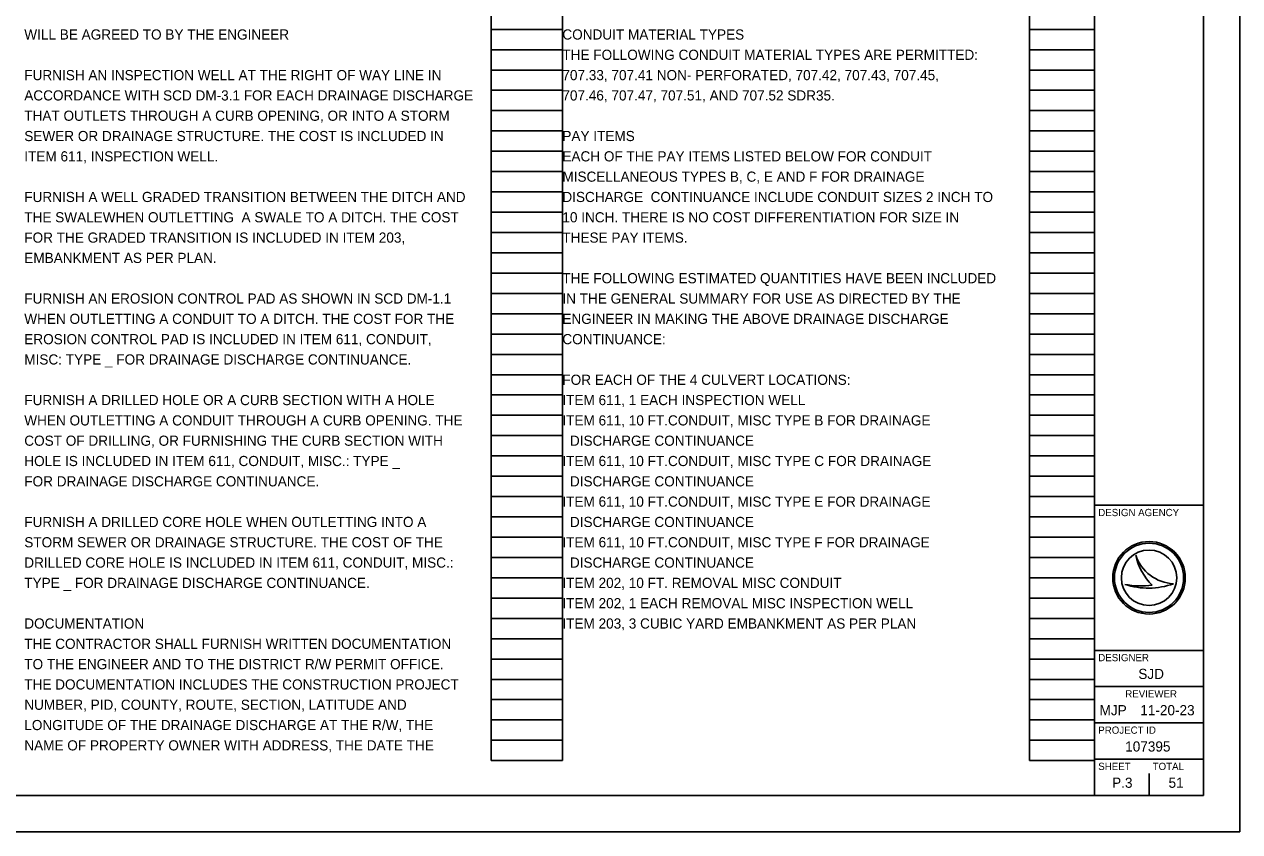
# Model space of a CAD drawing. Extents: x 0 to 34, y 0 to 22.
# Drawn here: x 17.24 to 34, y 0 to 11.13 of the extents above; entities that cross this region are included whole.
import ezdxf

# ---------------------------------------------------------------- set-up
doc = ezdxf.new("R2010")
doc.units = 0
for name, color, linetype in [('SH_Border', 7, 'Continuous'), ('SH_Cut_Line', 7, 'Continuous'), ('SH_Data', 7, 'Continuous'), ('SH_Text', 7, 'Continuous')]:
    doc.layers.add(name, color=color, linetype=linetype)

msp = doc.modelspace()

# ---------------------------------------------------------------- linework, layer by layer
at = {"layer": 'SH_Border'}
for p, q in [((32, 0.5), (32, 21.5)), ((32, 4.5), (33.5, 4.5)), ((32, 2.5), (33.5, 2.5)), ((32, 2), (33.5, 2)), ((32, 1.5), (33.5, 1.5)), ((32, 1), (33.5, 1))]:
    msp.add_line(p, q, dxfattribs=at)
msp.add_lwpolyline([(1.5, 21.5), (33.5, 21.5), (33.5, 0.5), (1.5, 0.5)], close=True, dxfattribs=at)
at = {"layer": 'SH_Cut_Line'}
msp.add_lwpolyline([(0, 0), (34, 0), (34, 22), (0, 22)], close=True, dxfattribs=at)
at = {"layer": 'SH_Data'}
for p, q in [((23.68, 0.98), (23.68, 21.14)), ((24.66, 0.98), (24.66, 21.14)), ((31.1, 0.98), (31.1, 21.14)), ((32, 0.98), (32, 21.14)), ((23.68, 11.06), (24.66, 11.06)), ((31.1, 11.06), (32, 11.06)), ((23.68, 10.78), (24.66, 10.78)), ((31.1, 10.78), (32, 10.78)), ((23.68, 10.5), (24.66, 10.5)), ((31.1, 10.5), (32, 10.5)), ((23.68, 10.22), (24.66, 10.22)), ((31.1, 10.22), (32, 10.22)), ((23.68, 9.94), (24.66, 9.94)), ((31.1, 9.94), (32, 9.94)), ((23.68, 9.66), (24.66, 9.66)), ((31.1, 9.66), (32, 9.66)), ((23.68, 9.38), (24.66, 9.38)), ((31.1, 9.38), (32, 9.38)), ((23.68, 9.1), (24.66, 9.1)), ((31.1, 9.1), (32, 9.1)), ((23.68, 8.82), (24.66, 8.82)), ((31.1, 8.82), (32, 8.82)), ((23.68, 8.54), (24.66, 8.54)), ((31.1, 8.54), (32, 8.54)), ((23.68, 8.26), (24.66, 8.26)), ((31.1, 8.26), (32, 8.26)), ((23.68, 7.98), (24.66, 7.98)), ((31.1, 7.98), (32, 7.98)), ((23.68, 7.7), (24.66, 7.7)), ((31.1, 7.7), (32, 7.7)), ((23.68, 7.42), (24.66, 7.42)), ((31.1, 7.42), (32, 7.42)), ((23.68, 7.14), (24.66, 7.14)), ((31.1, 7.14), (32, 7.14)), ((23.68, 6.86), (24.66, 6.86)), ((31.1, 6.86), (32, 6.86)), ((23.68, 6.58), (24.66, 6.58)), ((31.1, 6.58), (32, 6.58)), ((23.68, 6.3), (24.66, 6.3)), ((31.1, 6.3), (32, 6.3)), ((23.68, 6.02), (24.66, 6.02)), ((31.1, 6.02), (32, 6.02)), ((23.68, 5.74), (24.66, 5.74)), ((31.1, 5.74), (32, 5.74)), ((23.68, 5.46), (24.66, 5.46)), ((31.1, 5.46), (32, 5.46)), ((23.68, 5.18), (24.66, 5.18)), ((31.1, 5.18), (32, 5.18)), ((23.68, 4.9), (24.66, 4.9)), ((31.1, 4.9), (32, 4.9)), ((23.68, 4.62), (24.66, 4.62)), ((31.1, 4.62), (32, 4.62)), ((23.68, 4.34), (24.66, 4.34)), ((31.1, 4.34), (32, 4.34)), ((23.68, 4.06), (24.66, 4.06)), ((31.1, 4.06), (32, 4.06)), ((23.68, 3.78), (24.66, 3.78)), ((31.1, 3.78), (32, 3.78)), ((32.567, 3.81), (32.567, 3.81)), ((23.68, 3.5), (24.66, 3.5)), ((31.1, 3.5), (32, 3.5)), ((32.417, 3.41), (32.417, 3.41)), ((32.75, 3.5), (32.75, 3.5)), ((33.087, 3.419), (33.087, 3.419)), ((23.68, 3.22), (24.66, 3.22)), ((31.1, 3.22), (32, 3.22)), ((23.68, 2.94), (24.66, 2.94)), ((31.1, 2.94), (32, 2.94)), ((23.68, 2.66), (24.66, 2.66)), ((31.1, 2.66), (32, 2.66)), ((23.68, 2.38), (24.66, 2.38)), ((31.1, 2.38), (32, 2.38)), ((23.68, 2.1), (24.66, 2.1)), ((31.1, 2.1), (32, 2.1)), ((23.68, 1.82), (24.66, 1.82)), ((31.1, 1.82), (32, 1.82)), ((23.68, 1.54), (24.66, 1.54)), ((31.1, 1.54), (32, 1.54)), ((23.68, 1.26), (24.66, 1.26)), ((31.1, 1.26), (32, 1.26)), ((23.68, 0.98), (24.66, 0.98)), ((31.1, 0.98), (32, 0.98)), ((32.375, 0.675), (32.375, 0.675)), ((32.75, 0.5), (32.75, 0.8))]:
    msp.add_line(p, q, dxfattribs=at)
for radius in [0.5, 0.477, 0.477, 0.382]:
    msp.add_circle((32.75, 3.5), radius, dxfattribs=at)
for centre, radius, start, end in [((33.116, 3.998), 0.58, 198.9257, 198.9319), ((33.347, 3.97), 0.796, 191.6379, 191.6421), ((33.116, 3.998), 0.58, 198.9319, 267.1657), ((33.347, 3.97), 0.796, 191.6421, 226.0947), ((32.739, 4.37), 1.013, 251.4576, 290.0832), ((32.648, 4.654), 1.266, 259.4964, 259.4995), ((32.739, 4.37), 1.013, 251.4527, 251.4576), ((32.648, 4.654), 1.266, 259.4995, 276.6672)]:
    msp.add_arc(centre, radius, start, end, dxfattribs=at)

# ---------------------------------------------------------------- texts
for s, height, p in [('DESIGN AGENCY', 0.1, (32.05, 4.35)), ('DESIGNER', 0.1, (32.05, 2.35)), ('SJD', 0.14, (32.602, 2.105)), ('REVIEWER', 0.1, (32.422, 1.85)), ('MJP', 0.14, (32.068, 1.605)), ('11-20-23', 0.14, (32.629, 1.605)), ('PROJECT ID', 0.1, (32.05, 1.35)), ('107395', 0.14, (32.421, 1.105)), ('SHEET', 0.1, (32.05, 0.85)), ('TOTAL', 0.1, (32.8, 0.85)), ('P.3', 0.14, (32.241, 0.605)), ('51', 0.14, (33.019, 0.605))]:
    msp.add_text(s, height=height, dxfattribs=at).set_placement(p)
at = {"layer": 'SH_Text'}
for s, p in [('WILL BE AGREED TO BY THE ENGINEER', (17.24, 10.92)), ('CONDUIT MATERIAL TYPES', (24.66, 10.92)), ('THE FOLLOWING CONDUIT MATERIAL TYPES ARE PERMITTED:', (24.66, 10.64)), ('FURNISH AN INSPECTION WELL AT THE RIGHT OF WAY LINE IN', (17.24, 10.36)), ('707.33, 707.41 NON- PERFORATED, 707.42, 707.43, 707.45,', (24.66, 10.36)), ('ACCORDANCE WITH SCD DM-3.1 FOR EACH DRAINAGE DISCHARGE', (17.24, 10.08)), ('707.46, 707.47, 707.51, AND 707.52 SDR35.', (24.66, 10.08)), ('THAT OUTLETS THROUGH A CURB OPENING, OR INTO A STORM', (17.24, 9.8)), ('SEWER OR DRAINAGE STRUCTURE. THE COST IS INCLUDED IN', (17.24, 9.52)), ('PAY ITEMS', (24.66, 9.52)), ('ITEM 611, INSPECTION WELL.', (17.24, 9.24)), ('EACH OF THE PAY ITEMS LISTED BELOW FOR CONDUIT', (24.66, 9.24)), ('MISCELLANEOUS TYPES B, C, E AND F FOR DRAINAGE', (24.66, 8.96)), ('FURNISH A WELL GRADED TRANSITION BETWEEN THE DITCH AND', (17.24, 8.68)), ('DISCHARGE  CONTINUANCE INCLUDE CONDUIT SIZES 2 INCH TO', (24.66, 8.68)), ('THE SWALEWHEN OUTLETTING  A SWALE TO A DITCH. THE COST', (17.24, 8.4)), ('10 INCH. THERE IS NO COST DIFFERENTIATION FOR SIZE IN', (24.66, 8.4)), ('FOR THE GRADED TRANSITION IS INCLUDED IN ITEM 203,', (17.24, 8.12)), ('THESE PAY ITEMS.', (24.66, 8.12)), ('EMBANKMENT AS PER PLAN.', (17.24, 7.84)), ('THE FOLLOWING ESTIMATED QUANTITIES HAVE BEEN INCLUDED', (24.66, 7.56)), ('FURNISH AN EROSION CONTROL PAD AS SHOWN IN SCD DM-1.1', (17.24, 7.28)), ('IN THE GENERAL SUMMARY FOR USE AS DIRECTED BY THE', (24.66, 7.28)), ('WHEN OUTLETTING A CONDUIT TO A DITCH. THE COST FOR THE', (17.24, 7)), ('ENGINEER IN MAKING THE ABOVE DRAINAGE DISCHARGE', (24.66, 7)), ('EROSION CONTROL PAD IS INCLUDED IN ITEM 611, CONDUIT,', (17.24, 6.72)), ('CONTINUANCE:', (24.66, 6.72)), ('MISC: TYPE _ FOR DRAINAGE DISCHARGE CONTINUANCE.', (17.24, 6.44)), ('FOR EACH OF THE 4 CULVERT LOCATIONS:', (24.66, 6.16)), ('FURNISH A DRILLED HOLE OR A CURB SECTION WITH A HOLE', (17.24, 5.88)), ('ITEM 611, 1 EACH INSPECTION WELL', (24.66, 5.88)), ('WHEN OUTLETTING A CONDUIT THROUGH A CURB OPENING. THE', (17.24, 5.6)), ('ITEM 611, 10 FT.CONDUIT, MISC TYPE B FOR DRAINAGE', (24.66, 5.6)), ('COST OF DRILLING, OR FURNISHING THE CURB SECTION WITH', (17.24, 5.32)), ('  DISCHARGE CONTINUANCE', (24.66, 5.32)), ('HOLE IS INCLUDED IN ITEM 611, CONDUIT, MISC.: TYPE _', (17.24, 5.04)), ('ITEM 611, 10 FT.CONDUIT, MISC TYPE C FOR DRAINAGE', (24.66, 5.04)), ('FOR DRAINAGE DISCHARGE CONTINUANCE.', (17.24, 4.76)), ('  DISCHARGE CONTINUANCE', (24.66, 4.76)), ('ITEM 611, 10 FT.CONDUIT, MISC TYPE E FOR DRAINAGE', (24.66, 4.48)), ('FURNISH A DRILLED CORE HOLE WHEN OUTLETTING INTO A', (17.24, 4.2)), ('  DISCHARGE CONTINUANCE', (24.66, 4.2)), ('STORM SEWER OR DRAINAGE STRUCTURE. THE COST OF THE', (17.24, 3.92)), ('ITEM 611, 10 FT.CONDUIT, MISC TYPE F FOR DRAINAGE', (24.66, 3.92)), ('DRILLED CORE HOLE IS INCLUDED IN ITEM 611, CONDUIT, MISC.:', (17.24, 3.64)), ('  DISCHARGE CONTINUANCE', (24.66, 3.64)), ('TYPE _ FOR DRAINAGE DISCHARGE CONTINUANCE.', (17.24, 3.36)), ('ITEM 202, 10 FT. REMOVAL MISC CONDUIT', (24.66, 3.36)), ('ITEM 202, 1 EACH REMOVAL MISC INSPECTION WELL', (24.66, 3.08)), ('DOCUMENTATION', (17.24, 2.8)), ('ITEM 203, 3 CUBIC YARD EMBANKMENT AS PER PLAN', (24.66, 2.8)), ('THE CONTRACTOR SHALL FURNISH WRITTEN DOCUMENTATION', (17.24, 2.52)), ('TO THE ENGINEER AND TO THE DISTRICT R/W PERMIT OFFICE.', (17.24, 2.24)), ('THE DOCUMENTATION INCLUDES THE CONSTRUCTION PROJECT', (17.24, 1.96)), ('NUMBER, PID, COUNTY, ROUTE, SECTION, LATITUDE AND', (17.24, 1.68)), ('LONGITUDE OF THE DRAINAGE DISCHARGE AT THE R/W, THE', (17.24, 1.4)), ('NAME OF PROPERTY OWNER WITH ADDRESS, THE DATE THE', (17.24, 1.12))]:
    msp.add_text(s, height=0.14, dxfattribs=at).set_placement(p)

doc.saveas('drawing.dxf')
